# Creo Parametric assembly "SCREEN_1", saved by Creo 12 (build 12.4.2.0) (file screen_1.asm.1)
Units: Custom; MM, KILOGRAM, SECS

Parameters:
  PTC_WM_ITERATION = "0"
  PTC_WM_VERSION = "-.0"
  PTC_WM_LIFECYCLE_STATE = "In Work"
  PTC_WM_LIFECYCLE = "MO_CADDocument"
  PTC_WM_CREATED_BY = "Maximilian Roepper (Z0017RMS: MO)"
  PTC_WM_CREATED_ON = "18-Sep-26 11:36:42 AM"
  PTC_WM_MODIFIED_BY = "Maximilian Roepper (Z0017RMS: MO)"
  PTC_WM_MODIFIED_ON = "18-Sep-26 11:36:46 AM"
  PDMLINKNUMBER = "PDM000071454860"
  PTC_WM_NAME = "screen_1.asm"
  PTC_WM_NUMBER = "PDM000071454860"

Other parameters: WEIGHT, WEIGHT_FACTOR, WEIGHT_ADD, MC_ERRORS, SUPPLIER, ISPOSITIONINGASSEMBLY

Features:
  1. coordinate system
  2. imported feature
  3. component "SCREEN_FILM_1"
  4. component "SCREEN_GLASS_1"

Other named items: DRW_VIEW_ORG, ROUGH-GROB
